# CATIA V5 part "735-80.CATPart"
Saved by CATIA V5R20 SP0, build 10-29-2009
Part number: 735-80
Bounding box of the stored display mesh (mm): x -59 to 59, y -59 to 59, z -60 to 60
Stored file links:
  C:\Users\Utente\Desktop\IO LAVORO\3D X SITO CF\X SITO\735\735-80.CATPart
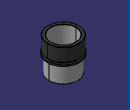
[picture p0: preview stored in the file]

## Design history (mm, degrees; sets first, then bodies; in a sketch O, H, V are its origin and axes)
Set1
  DatumSurface1 to DatumSurface25 "735-80"
Body1 (main body)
